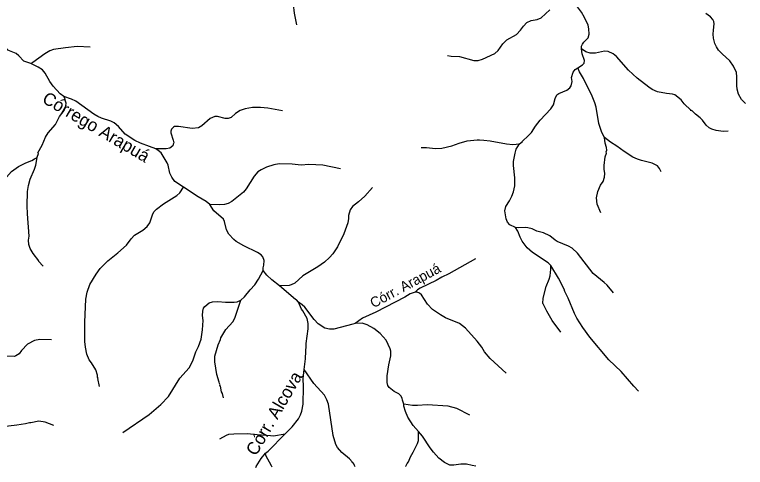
# Model space of a CAD drawing. Extents: x 280.4 to 335.6, y 8893.9 to 8949.5.
# Drawn here: x 309.86 to 321.39, y 8894.1 to 8901.25 of the extents above; entities that cross this region are included whole.
import ezdxf
from ezdxf.enums import TextEntityAlignment as Align

# ---------------------------------------------------------------- set-up
doc = ezdxf.new("R2010")
doc.units = 0
doc.header["$LTSCALE"] = 0.064
doc.layers.add('61', color=7, linetype='Continuous')
doc.layers.add('7', color=7, linetype='Continuous', lineweight=25)

msp = doc.modelspace()

# ---------------------------------------------------------------- linework, layer by layer
at = {"layer": '7'}
for points in [[(314.3162, 8901.0901), (314.2764, 8901.2731), (314.2619, 8901.4067), (314.2541, 8901.4306), (314.2521, 8901.6335), (314.2444, 8901.6985), (314.2307, 8901.7454), (314.1801, 8901.8358), (314.0271, 8902.188), (313.9963, 8902.2805), (313.9759, 8902.3735), (313.9533, 8902.5315), (313.953, 8902.845), (313.9418, 8902.8897), (313.894, 8902.9978), (313.8466, 8903.063), (313.7965, 8903.1081), (313.7048, 8903.1761), (313.6184, 8903.2544), (313.5855, 8903.2922), (313.5391, 8903.3653)], [(318.8055, 8900.7094), (318.8063, 8900.7193), (318.8088, 8900.7501), (318.8224, 8900.7832), (318.8433, 8900.8126), (318.914, 8900.8845), (318.9268, 8900.9396), (318.9237, 8901.0268), (318.9113, 8901.0835), (318.8562, 8901.2009), (318.8053, 8901.2866), (318.6961, 8901.4355), (318.6556, 8901.5247), (318.5867, 8901.5987)], [(316.6929, 8900.6019), (316.7524, 8900.5922), (316.8837, 8900.5876), (317.1094, 8900.5223), (317.1756, 8900.5273), (317.247, 8900.5453), (317.4422, 8900.637), (317.4904, 8900.6804), (317.5671, 8900.7854), (317.63, 8900.8484), (317.7818, 8900.9364), (317.8472, 8901.0012), (317.8918, 8901.0657), (317.9466, 8901.1219), (318.0114, 8901.1566), (318.1097, 8901.1735), (318.1713, 8901.1968), (318.3062, 8901.3228)], [(321.3939, 8899.8454), (321.3333, 8899.91), (321.2853, 8899.9943), (321.2667, 8900.0743), (321.2605, 8900.1313), (321.2602, 8900.2689), (321.252, 8900.3334), (321.2087, 8900.4363), (321.1493, 8900.5178), (321.0265, 8900.6282), (320.9695, 8900.6889), (320.9372, 8900.7397), (320.9127, 8900.7937), (320.8893, 8900.8773), (320.8847, 8900.9398), (320.8923, 8901.0052), (320.9036, 8901.1022), (320.8938, 8901.1427), (320.878, 8901.1714), (320.8408, 8901.215), (320.7708, 8901.2648)], [(310.1207, 8900.4791), (310.0064, 8900.5161), (309.9304, 8900.5994), (309.887, 8900.6352), (309.7568, 8900.6881), (309.7116, 8900.7244), (309.6623, 8900.8292), (309.6234, 8900.8777), (309.5164, 8900.9176), (309.4519, 8900.9694), (309.4104, 8901.0117), (309.3449, 8901.029), (309.2738, 8901.0325), (309.2074, 8901.0624), (309.1704, 8901.0943), (309.1396, 8901.1351), (309.1219, 8901.1876), (309.0992, 8901.2385)], [(311.0525, 8900.7371), (310.8474, 8900.7443), (310.6651, 8900.7268), (310.4757, 8900.6995), (310.4188, 8900.6773), (310.3388, 8900.63), (310.1507, 8900.4917), (310.1207, 8900.4791)], [(318.7524, 8900.4098), (318.8245, 8900.4583), (318.8498, 8900.4824), (318.8545, 8900.5266), (318.8178, 8900.6294), (318.8055, 8900.7094)], [(321.1236, 8899.4073), (321.0443, 8899.406), (320.9339, 8899.4184), (320.8659, 8899.4392), (320.8233, 8899.4626), (320.7762, 8899.503), (320.7158, 8899.5838), (320.6816, 8899.6184), (320.6048, 8899.6752), (320.5466, 8899.7344), (320.5345, 8899.7326), (320.5322, 8899.7415), (320.4292, 8899.8388), (320.3817, 8899.9066), (320.2799, 8899.9815), (320.2432, 8899.9923), (320.1508, 8900.0015), (320.0085, 8900.0306), (319.9255, 8900.0676), (319.8711, 8900.1031), (319.6858, 8900.246), (319.5518, 8900.3738), (319.3593, 8900.5856), (319.3059, 8900.6309), (319.2307, 8900.6692), (319.1733, 8900.6725), (319.0308, 8900.6408), (318.943, 8900.639), (318.8743, 8900.6636), (318.8055, 8900.7094)], [(310.6405, 8899.9567), (310.5821, 8899.9962), (310.469, 8900.1174), (310.4192, 8900.191), (310.3461, 8900.3255), (310.3015, 8900.3786), (310.2327, 8900.4218), (310.1207, 8900.4791)], [(317.8301, 8899.2097), (317.8759, 8899.2465), (317.8763, 8899.2538), (317.9684, 8899.3351), (318.0164, 8899.3878), (318.083, 8899.4896), (318.1565, 8899.5856), (318.3256, 8899.7594), (318.3654, 8899.8249), (318.3911, 8899.9254), (318.4196, 8899.9841), (318.4495, 8900.0059), (318.5756, 8900.0556), (318.6226, 8900.0932), (318.6465, 8900.1254), (318.6581, 8900.192), (318.6522, 8900.2583), (318.6748, 8900.3384), (318.7086, 8900.3803), (318.7524, 8900.4098)], [(319.1684, 8899.3108), (319.1283, 8899.3875), (319.0839, 8899.5331), (319.0374, 8899.789), (319.0194, 8899.8543), (318.9762, 8899.9599), (318.8389, 8900.2407), (318.7785, 8900.3456), (318.7524, 8900.4098)], [(310.2165, 8898.9957), (310.2173, 8899.0003), (310.2373, 8899.0569), (310.2296, 8899.0666), (310.2976, 8899.1891), (310.3521, 8899.317), (310.3944, 8899.3813), (310.5052, 8899.5147), (310.5723, 8899.6399), (310.6454, 8899.7363), (310.6729, 8899.8082), (310.6763, 8899.8507), (310.6569, 8899.9127), (310.6614, 8899.9217), (310.6405, 8899.9567)], [(312.0925, 8899.1297), (311.9925, 8899.1692), (311.8471, 8899.221), (311.7582, 8899.2626), (311.6066, 8899.3633), (311.502, 8899.4821), (311.4334, 8899.5386), (311.3784, 8899.5674), (311.2344, 8899.6138), (311.1776, 8899.639), (311.114, 8899.6782), (310.8273, 8899.8852), (310.7611, 8899.916), (310.6405, 8899.9567)], [(314.0899, 8899.7308), (313.8593, 8899.7749), (313.7447, 8899.7849), (313.6174, 8899.7817), (313.4984, 8899.7628), (313.4225, 8899.7347), (313.3491, 8899.6892), (313.282, 8899.6257), (313.2346, 8899.6078), (313.1849, 8899.6101), (313.0656, 8899.6407), (313.0203, 8899.6401), (312.9482, 8899.607), (312.8189, 8899.4931), (312.7626, 8899.4634), (312.6648, 8899.4523), (312.4483, 8899.4857), (312.387, 8899.482), (312.3686, 8899.4739), (312.3388, 8899.4403), (312.3273, 8899.4116), (312.3285, 8899.3812), (312.3648, 8899.2658), (312.3728, 8899.2252), (312.3669, 8899.2026), (312.3573, 8899.1797), (312.3098, 8899.1436), (312.2521, 8899.1321), (312.1675, 8899.1293), (312.0925, 8899.1297)], [(319.1111, 8898.1198), (319.055, 8898.2577), (319.0437, 8898.3554), (319.0648, 8898.4594), (319.1094, 8898.558), (319.1478, 8898.6149), (319.1709, 8898.6823), (319.1764, 8898.7437), (319.1638, 8898.8106), (319.1637, 8898.8685), (319.1824, 8899.0037), (319.2019, 8899.0619), (319.1988, 8899.0825), (319.2052, 8899.1077), (319.2004, 8899.1525), (319.1827, 8899.2181), (319.1684, 8899.3108)], [(320.0674, 8898.7688), (320.0392, 8898.8215), (320.0049, 8898.8603), (319.9248, 8898.9037), (319.7571, 8898.9442), (319.6907, 8898.9665), (319.6179, 8899.0013), (319.4799, 8899.09), (319.3649, 8899.1747), (319.2679, 8899.234), (319.1684, 8899.3108)], [(316.2791, 8899.1492), (316.3596, 8899.1529), (316.5063, 8899.1374), (316.6023, 8899.1422), (316.7615, 8899.1789), (316.8755, 8899.2226), (317.0035, 8899.2576), (317.1596, 8899.2715), (317.1984, 8899.2709), (317.2668, 8899.2699), (317.3675, 8899.2578), (317.6217, 8899.2072), (317.725, 8899.1996), (317.8301, 8899.2097)], [(317.7639, 8897.8916), (317.6772, 8897.9335), (317.6386, 8897.9728), (317.6188, 8898.0242), (317.5965, 8898.1513), (317.6122, 8898.2187), (317.6719, 8898.3127), (317.7085, 8898.3856), (317.734, 8898.4535), (317.7574, 8898.5458), (317.7563, 8898.675), (317.734, 8898.8702), (317.7371, 8898.9325), (317.7595, 8899.0604), (317.7794, 8899.126), (317.8301, 8899.2097)], [(312.5275, 8898.5248), (312.3899, 8898.6141), (312.344, 8898.684), (312.3138, 8898.7478), (312.2853, 8898.8742), (312.2684, 8898.9114), (312.1737, 8899.0661), (312.13, 8899.1061), (312.0925, 8899.1297)], [(309.195, 8897.8199), (309.2389, 8897.9471), (309.2482, 8897.9544), (309.3024, 8898.0715), (309.3866, 8898.2164), (309.5301, 8898.4052), (309.6345, 8898.5211), (309.6767, 8898.5791), (309.7335, 8898.6818), (309.8117, 8898.7712), (309.9263, 8898.8525), (310.0414, 8898.9085), (310.1367, 8898.9467), (310.1753, 8898.9753), (310.2165, 8898.9957)], [(310.3149, 8897.2791), (310.2415, 8897.3554), (310.242, 8897.3627), (310.1526, 8897.4783), (310.1082, 8897.5583), (310.0879, 8897.6212), (310.0815, 8897.6907), (310.0924, 8897.7546), (310.0639, 8898.1066), (310.0591, 8898.2336), (310.0672, 8898.4598), (310.0824, 8898.5522), (310.1082, 8898.6494), (310.1762, 8898.8081), (310.1963, 8898.8742), (310.2165, 8898.9957)], [(315.0057, 8898.8152), (314.7272, 8898.8732), (314.5065, 8898.8813), (314.3834, 8898.875), (314.2426, 8898.8908), (314.038, 8898.8924), (313.9505, 8898.8806), (313.8387, 8898.8432), (313.7518, 8898.8013), (313.699, 8898.7661), (313.6409, 8898.7016), (313.517, 8898.5014), (313.4761, 8898.4476), (313.2905, 8898.2973), (313.2335, 8898.2689), (313.1732, 8898.2541), (313.0912, 8898.245), (312.9438, 8898.253)], [(311.2008, 8895.3776), (311.1758, 8895.5072), (311.1794, 8895.5128), (311.1721, 8895.5234), (311.1685, 8895.5563), (311.1421, 8895.643), (311.0781, 8895.7557), (311.0414, 8895.8014), (310.9994, 8895.8885), (310.9784, 8896.0019), (310.9707, 8896.089), (310.969, 8896.397), (310.9851, 8896.76), (311.0055, 8896.8667), (311.0506, 8896.9878), (311.1509, 8897.1503), (311.2148, 8897.2415), (311.331, 8897.3656), (311.4891, 8897.4921), (311.6259, 8897.6128), (311.7004, 8897.7112), (311.7537, 8897.766), (311.8843, 8897.8488), (311.9546, 8897.9063), (311.9944, 8897.9609), (312.043, 8898.1055), (312.0628, 8898.1403), (312.1, 8898.1805), (312.2123, 8898.2611), (312.4201, 8898.3924), (312.4709, 8898.4374), (312.5275, 8898.5248)], [(312.9438, 8898.253), (312.8852, 8898.3015), (312.7602, 8898.3737), (312.5275, 8898.5248)], [(315.5087, 8898.5199), (315.3872, 8898.3835), (315.2907, 8898.2966), (315.1952, 8898.2217), (315.1549, 8898.167), (315.1336, 8898.0811), (315.1334, 8898.0337), (315.1208, 8897.9609), (315.0567, 8897.7874), (314.9592, 8897.5834), (314.8844, 8897.4745), (314.8301, 8897.4154), (314.7506, 8897.344), (314.6451, 8897.2704), (314.412, 8897.1279), (314.282, 8897.0115), (314.2266, 8896.9837), (314.1956, 8896.9765), (314.0444, 8896.9678)], [(313.7862, 8897.213), (313.7844, 8897.2531), (313.7965, 8897.2949), (313.8027, 8897.3708), (313.7805, 8897.4252), (313.7525, 8897.4573), (313.6958, 8897.4939), (313.4773, 8897.6), (313.3604, 8897.6678), (313.3219, 8897.6974), (313.2428, 8897.7849), (313.204, 8897.853), (313.1729, 8897.9818), (313.1567, 8898.0203), (313.0084, 8898.1512), (312.9438, 8898.253)], [(318.3233, 8897.2905), (318.323, 8897.291), (318.2841, 8897.3328), (318.034, 8897.4952), (317.9503, 8897.5678), (317.8727, 8897.673), (317.8404, 8897.7378), (317.8057, 8897.8322), (317.7639, 8897.8916)], [(319.3115, 8896.8607), (319.2125, 8896.9772), (319.1647, 8897.0235), (318.9934, 8897.1646), (318.7462, 8897.4835), (318.6623, 8897.5619), (318.6013, 8897.5952), (318.4263, 8897.6667), (318.3906, 8897.6872), (318.3101, 8897.7556), (318.2088, 8897.806), (318.1018, 8897.8339), (318.0306, 8897.8676), (317.9626, 8897.8863), (317.925, 8897.8897), (317.821, 8897.8835), (317.7639, 8897.8916)], [(317.1355, 8897.3957), (316.7141, 8897.156), (316.6048, 8897.1045), (316.5168, 8897.0534), (316.2594, 8896.9333), (316.2183, 8896.9034), (316.1844, 8896.8685)], [(318.4815, 8896.2392), (318.346, 8896.4191), (318.2601, 8896.5673), (318.2041, 8896.6863), (318.1979, 8896.6882), (318.202, 8896.7726), (318.2505, 8896.959), (318.2999, 8897.0758), (318.3126, 8897.1247), (318.3256, 8897.2342), (318.3233, 8897.2905)], [(319.7093, 8895.3063), (319.6311, 8895.3833), (319.4322, 8895.6172), (319.2416, 8895.8001), (318.9409, 8896.1604), (318.8302, 8896.3105), (318.7326, 8896.4584), (318.697, 8896.5301), (318.5997, 8896.7719), (318.5468, 8896.8784), (318.5337, 8896.9171), (318.4443, 8897.0895), (318.3233, 8897.2905)], [(313.4295, 8896.7405), (313.489, 8896.794), (313.5786, 8896.9043), (313.6546, 8896.9853), (313.7116, 8897.0735), (313.7862, 8897.213)], [(314.0444, 8896.9678), (313.9203, 8897.064), (313.8429, 8897.1385), (313.7862, 8897.213)], [(314.342, 8896.7106), (314.3094, 8896.7478), (314.2927, 8896.7555), (314.0444, 8896.9678)], [(316.1844, 8896.8685), (316.1038, 8896.8401), (316.021, 8896.7888), (315.5605, 8896.5537), (315.3503, 8896.4564), (315.2347, 8896.3723)], [(317.6188, 8895.5892), (317.3649, 8895.8199), (317.2789, 8895.9296), (317.2377, 8895.9984), (317.1622, 8896.0974), (316.9754, 8896.2989), (316.8814, 8896.3743), (316.6636, 8896.4656), (316.583, 8896.5103), (316.4565, 8896.5956), (316.3778, 8896.6792), (316.2824, 8896.8254), (316.2512, 8896.8518), (316.2161, 8896.8678), (316.1844, 8896.8685)], [(311.5716, 8894.6554), (311.987, 8894.9366), (312.1679, 8895.0971), (312.2886, 8895.2229), (312.4692, 8895.5101), (312.6157, 8895.6735), (312.6725, 8895.7826), (312.7211, 8895.9286), (312.7617, 8896.0123), (312.8051, 8896.1282), (312.829, 8896.2729), (312.837, 8896.4218), (312.829, 8896.5024), (312.8331, 8896.5686), (312.8455, 8896.6141), (312.8637, 8896.6446), (312.93, 8896.6991), (312.9841, 8896.7174), (313.0712, 8896.7239), (313.1927, 8896.7127), (313.3243, 8896.7097), (313.3759, 8896.7187), (313.4295, 8896.7405)], [(313.1579, 8895.1993), (313.1409, 8895.2712), (313.1285, 8895.2937), (313.109, 8895.3854), (313.1028, 8895.3894), (313.1052, 8895.4043), (313.093, 8895.4275), (313.0912, 8895.4502), (313.0529, 8895.5677), (313.0225, 8895.7698), (313.0242, 8895.8594), (313.0741, 8896.0393), (313.1115, 8896.1204), (313.1156, 8896.1463), (313.1975, 8896.2781), (313.3035, 8896.3987), (313.3375, 8896.4584), (313.4295, 8896.7405)], [(315.2347, 8896.3723), (315.1976, 8896.3623), (314.9007, 8896.2827), (314.8326, 8896.2838), (314.7601, 8896.3), (314.6544, 8896.3682), (314.5909, 8896.4351), (314.441, 8896.6311), (314.3994, 8896.6711), (314.342, 8896.7106)], [(314.4322, 8895.6459), (314.4512, 8895.8193), (314.4521, 8895.8275), (314.4648, 8896.0275), (314.462, 8896.0577), (314.4937, 8896.2881), (314.4937, 8896.3753), (314.4774, 8896.4518), (314.4121, 8896.5752), (314.3907, 8896.6008), (314.342, 8896.7106)], [(316.0041, 8895.1013), (315.9931, 8895.1351), (315.9855, 8895.1644), (315.9771, 8895.198), (315.957, 8895.2354), (315.9238, 8895.2636), (315.8494, 8895.3006), (315.7745, 8895.3632), (315.7532, 8895.3953), (315.7396, 8895.4446), (315.7396, 8895.5477), (315.7652, 8895.7244), (315.7984, 8895.8634), (315.7969, 8895.9363), (315.7885, 8895.9722), (315.7267, 8896.1114), (315.6298, 8896.2164), (315.5308, 8896.2964), (315.427, 8896.3548), (315.3477, 8896.3783), (315.2347, 8896.3723)], [(310.4425, 8896.1158), (310.2596, 8896.1194), (310.1756, 8896.1059), (310.0659, 8896.0475), (309.9736, 8895.9501), (309.933, 8895.8976), (309.881, 8895.862), (309.8586, 8895.8556), (309.7387, 8895.8562), (309.7048, 8895.8492), (309.5456, 8895.8523), (309.4505, 8895.8397), (309.3537, 8895.8123), (309.1625, 8895.7296), (308.9812, 8895.6172), (308.9113, 8895.5553), (308.8192, 8895.4471), (308.8132, 8895.4362)], [(314.131, 8894.6314), (314.2409, 8894.7434), (314.3396, 8894.8703), (314.3735, 8894.9305), (314.3966, 8894.9903), (314.4137, 8895.1031), (314.4203, 8895.3723), (314.4171, 8895.5076), (314.4322, 8895.6459)], [(315.2372, 8894.1116), (315.2274, 8894.1309), (315.2086, 8894.1678), (315.1926, 8894.1755), (315.1876, 8894.1921), (315.1456, 8894.2408), (315.0274, 8894.3384), (314.9592, 8894.4179), (314.932, 8894.4673), (314.8891, 8894.6064), (314.8137, 8895.0999), (314.7898, 8895.1703), (314.7512, 8895.2414), (314.5845, 8895.4296), (314.4322, 8895.6459)], [(316.2338, 8894.6687), (316.1494, 8894.7634), (316.0694, 8894.8985), (316.032, 8894.9862), (316.0068, 8895.0712), (316.0041, 8895.1013)], [(317.0458, 8894.9261), (316.8382, 8895.0303), (316.7022, 8895.0684), (316.372, 8895.091), (316.2177, 8895.0784), (316.1395, 8895.0784), (316.0041, 8895.1013)], [(310.4826, 8894.7629), (310.3421, 8894.8175), (310.242, 8894.8305), (310.1196, 8894.8083), (310.0957, 8894.8093), (310.0349, 8894.7908), (309.8969, 8894.768), (309.5865, 8894.7325), (309.4087, 8894.6953), (309.2284, 8894.6448), (309.0754, 8894.6242), (308.9013, 8894.621), (308.8045, 8894.6309), (308.4493, 8894.7071), (308.3789, 8894.731), (308.2967, 8894.7342), (308.2016, 8894.6955), (308.1509, 8894.661)], [(313.1019, 8894.556), (313.2073, 8894.6127), (313.2448, 8894.6256), (313.3192, 8894.6337), (313.5303, 8894.6401), (313.6912, 8894.6212), (313.8978, 8894.6059), (313.9483, 8894.6021), (314.131, 8894.6314)], [(313.8212, 8894.3257), (313.8622, 8894.3573), (314.131, 8894.6314)], [(316.0331, 8894.1157), (316.0371, 8894.1239), (316.0564, 8894.1636), (316.0768, 8894.1892), (316.1103, 8894.2715), (316.1526, 8894.3433), (316.2203, 8894.4817), (316.2335, 8894.5289), (316.2338, 8894.6687)], [(317.1379, 8894.1212), (317.0818, 8894.1344), (316.9918, 8894.1555), (316.9054, 8894.1555), (316.791, 8894.1396), (316.73, 8894.1398), (316.6442, 8894.1784), (316.5574, 8894.2509), (316.4708, 8894.3457), (316.4172, 8894.4144), (316.2987, 8894.596), (316.2338, 8894.6687)], [(313.6676, 8894.1036), (313.6761, 8894.1179), (313.7518, 8894.245), (313.8212, 8894.3257)], [(313.9254, 8894.1049), (313.9144, 8894.1259), (313.8286, 8894.29), (313.8212, 8894.3257)]]:
    msp.add_lwpolyline(points, dxfattribs=at)

# ---------------------------------------------------------------- texts
at = {"layer": '61'}
for s, height, rotation, p in [('Córrego Arapuá', 0.2, 329.534, (311.1007, 8899.3904)), ('Córr. Arapuá', 0.16, 28.301, (316.0643, 8896.9035)), ('Córr. Alcova', 0.2, 59.831, (314.0421, 8894.9073))]:
    msp.add_text(s, height=height, rotation=rotation, dxfattribs=at).set_placement(p, align=Align.CENTER)

doc.saveas('drawing.dxf')
